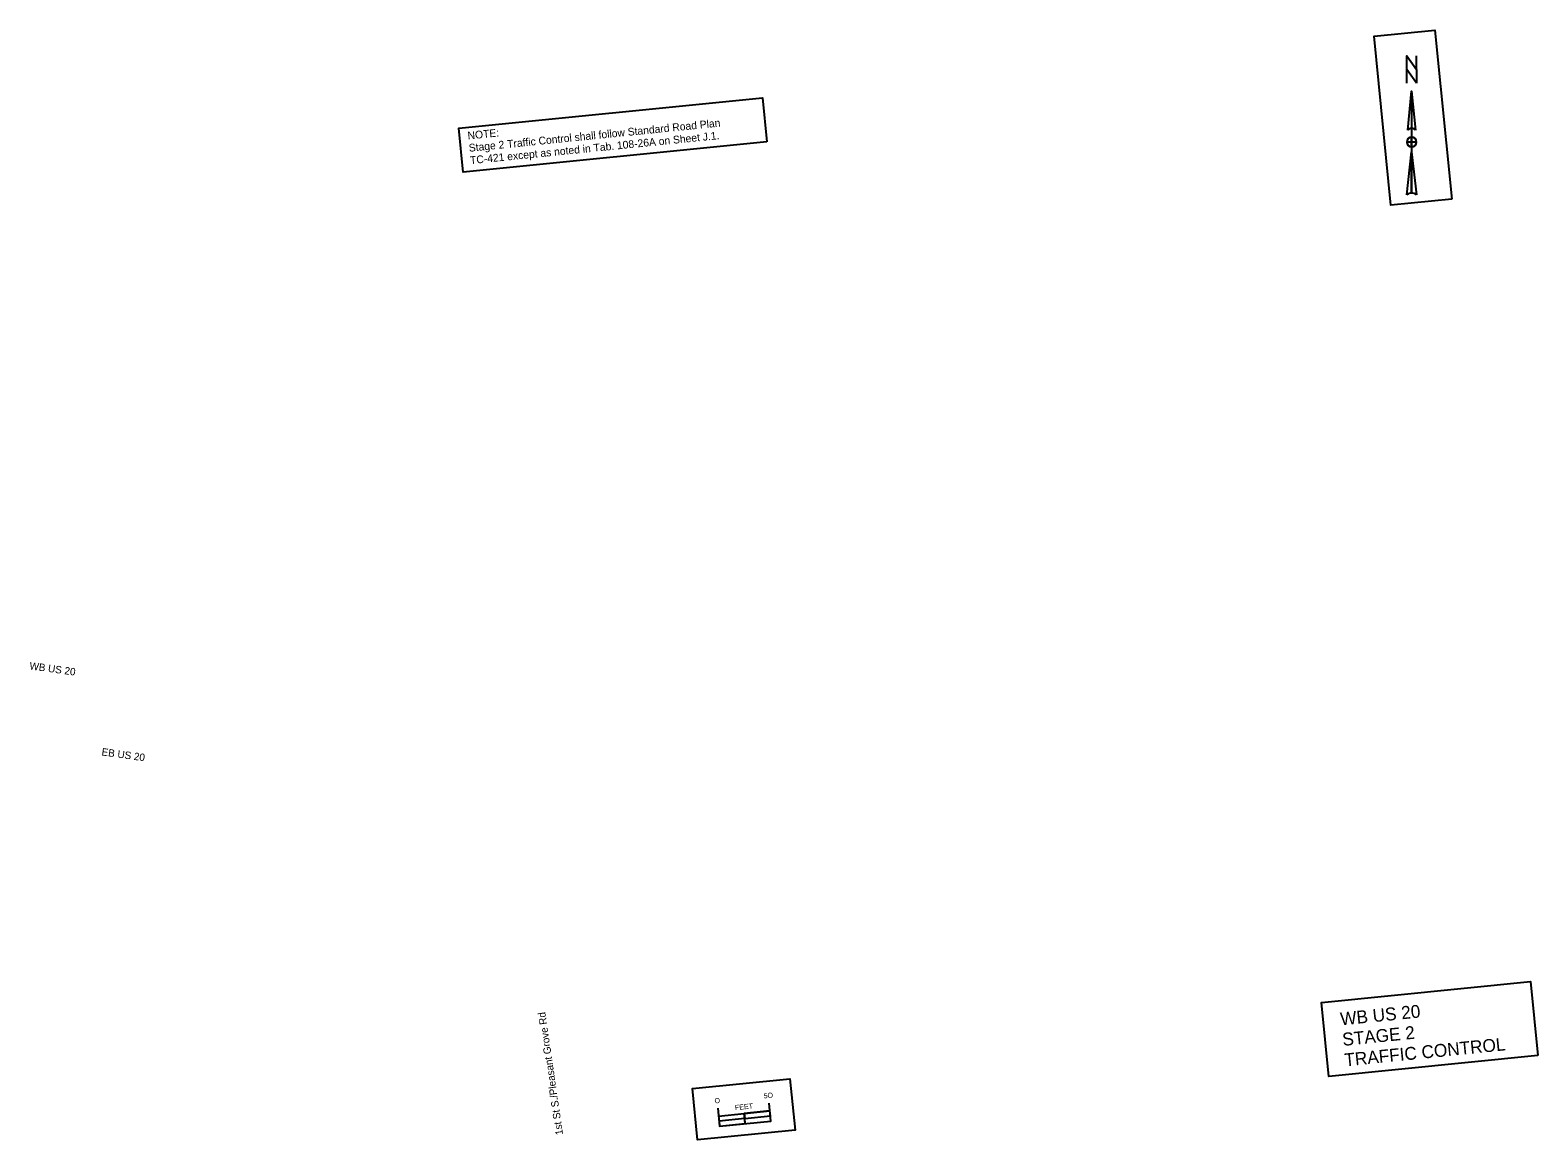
# Model space of a CAD drawing. Extents: x 21371983 to 21373446, y 8397223 to 8398300.
import ezdxf

# ---------------------------------------------------------------- set-up
doc = ezdxf.new("R2010")
doc.units = 0
for name, color, linetype in [('Default', 7, 'Continuous'), ('SheetAddenda', 7, 'Continuous'), ('SheetText', 7, 'Continuous')]:
    doc.layers.add(name, color=color, linetype=linetype)

msp = doc.modelspace()

# ---------------------------------------------------------------- linework, layer by layer
at = {"layer": 'Default'}
for points in [[(21373362.8, 8398135.6), (21373303.7, 8398129.7), (21373287.3, 8398293.6), (21373346.4, 8398299.6)], [(21372698.2, 8398191.3), (21372403.3, 8398161.7), (21372399, 8398204.4), (21372693.9, 8398234)], [(21373446.3, 8397304.6), (21373243.5, 8397284.2), (21373236.3, 8397355.8), (21373439.1, 8397376.2)]]:
    msp.add_lwpolyline(points, close=True, dxfattribs=at)
at = {"layer": 'SheetAddenda'}
for p, q in [((21373323.8, 8398240.4), (21373327.6, 8398202.4)), ((21373323.8, 8398240.4), (21373323.8, 8398141.5)), ((21373320, 8398202.4), (21373320, 8398202.4)), ((21373320.1, 8398202.7), (21373320.8, 8398203.5)), ((21373319, 8398139.6), (21373323.8, 8398181.5)), ((21373323.8, 8398186.2), (21373323.8, 8398186.2))]:
    msp.add_line(p, q, dxfattribs=at)
msp.add_lwpolyline([(21373328.5, 8398248), (21373319, 8398261.3), (21373319, 8398274.6), (21373328.5, 8398261.3)], close=True, dxfattribs=at)
for points in [[(21373319, 8398248), (21373319, 8398274.6), (21373328.5, 8398261.3), (21373328.5, 8398274.6)], [(21373320, 8398202.4), (21373323.8, 8398240.4), (21373323.8, 8398204.3)], [(21373328.5, 8398191), (21373323.8, 8398191), (21373323.8, 8398195.7)], [(21373323.8, 8398186.2), (21373323.8, 8398191), (21373319, 8398191)], [(21373323.8, 8398141.5), (21373323.8, 8398181.5), (21373328.5, 8398139.6)]]:
    msp.add_lwpolyline(points, dxfattribs=at)
for centre, radius, start, end in [((21373323.8, 8398191), 4.75, 90, 180), ((21373323.8, 8398199.5), 4.75, 90.0204, 143.1257), ((21373323.8, 8398199.5), 4.75, 36.8481, 90.0218), ((21373323.8, 8398191), 4.75, 0, 90), ((21373323.8, 8398191), 4.75, 180, 270), ((21373323.8, 8398191), 4.75, 270, 360), ((21373323.8, 8398134.6), 6.89, 89.9894, 133.619), ((21373323.8, 8398134.6), 6.89, 46.4021, 90.0006)]:
    msp.add_arc(centre, radius, start, end, dxfattribs=at)
at = {"layer": 'SheetText'}
msp.add_line((21372677.1, 8397238.4), (21372676.1, 8397248.3), dxfattribs=at)
msp.add_line((21372677.1, 8397238.4), (21372676.1, 8397248.3), dxfattribs=at)
for points in [[(21372625.9, 8397272.4), (21372720.5, 8397281.9), (21372725.4, 8397232.2), (21372630.9, 8397222.7)], [(21372625.9, 8397272.4), (21372720.5, 8397281.9), (21372725.4, 8397232.2), (21372630.9, 8397222.7)], [(21372630.9, 8397222.7), (21372625.9, 8397272.4), (21372720.5, 8397281.9), (21372725.4, 8397232.2)], [(21372676.6, 8397243.4), (21372701.5, 8397245.9), (21372701, 8397250.8), (21372676.1, 8397248.3)], [(21372652.2, 8397235.9), (21372677.1, 8397238.4), (21372676.6, 8397243.4), (21372651.7, 8397240.9)]]:
    msp.add_lwpolyline(points, close=True, dxfattribs=at)
for points in [[(21372650.5, 8397253.3), (21372652.2, 8397235.9), (21372702, 8397240.9), (21372700.2, 8397258.3)], [(21372651.2, 8397245.8), (21372701, 8397250.8)]]:
    msp.add_lwpolyline(points, dxfattribs=at)

# ---------------------------------------------------------------- texts
at = {"layer": 'Default'}
for s, height, p in [('Stage 2 Traffic Control shall follow Standard Road Plan', 7.5, (21372409.2, 8398181.5)), ('NOTE:', 7.5, (21372408, 8398193.4)), ('TC-421 except as noted in Tab. 108-26A on Sheet J.1.', 7.5, (21372410.4, 8398169.5)), ('WB US 20', 12.5, (21373255.2, 8397333.7)), ('STAGE 2', 12.5, (21373257.2, 8397313.8)), ('TRAFFIC CONTROL', 12.5, (21373259.2, 8397293.9))]:
    msp.add_text(s, height=height, rotation=5.7358, dxfattribs=at).set_placement(p)
at = {"layer": 'SheetAddenda'}
for s, rotation, p in [('WB US 20', 352.1262, (21371982.1, 8397679.3)), ('EB US 20', 352.1262, (21372052.1, 8397595.8)), ('1st St S./Pleasant Grove Rd', 98.2476, (21372500.3, 8397227.9))]:
    msp.add_text(s, height=7.2, rotation=rotation, dxfattribs=at).set_placement(p)
at = {"layer": 'SheetText'}
for s, p in [('O', (21372647.5, 8397258)), ('5O', (21372695.1, 8397262.8)), ('FEET', (21372667.3, 8397251.4))]:
    msp.add_text(s, height=5, rotation=5.7358, dxfattribs=at).set_placement(p)

doc.saveas('drawing.dxf')
